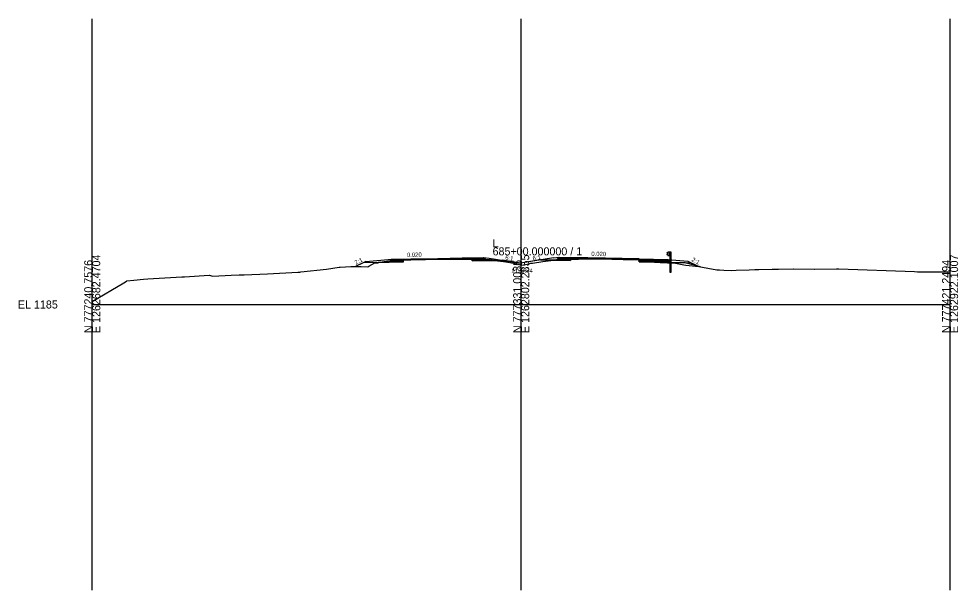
# Model space of a CAD drawing. Extents: x -41 to 1262860, y -100 to 777489.
# Drawn here: x 974.3 to 1302.8, y 970 to 1170 of the extents above; entities that cross this region are included whole.
import ezdxf

# ---------------------------------------------------------------- set-up
doc = ezdxf.new("R2010")
doc.units = 0
for name, color, linetype in [('Exist Cross Section Cell', 7, 'Continuous'), ('Exist XS Center Line Elevation Label', 7, 'Continuous'), ('Exist XS Ground Line', 7, 'Continuous'), ('Prop CMT Guardrail Graphics', 7, 'Continuous'), ('Prop CMT Pvmt Course 1', 7, 'Continuous'), ('Prop CMT Pvmt Milling', 7, 'Continuous'), ('Prop CMT Pvmt Surface', 7, 'Continuous'), ('Prop CMT Shld Paved Course 1', 7, 'Continuous'), ('Prop CMT Shld Paved Course 2', 7, 'Continuous'), ('Prop CMT Shld Paved Course 4', 7, 'Continuous'), ('Prop CMT Subgrade Earthwork', 7, 'Continuous'), ('Prop XS Earthwork Shape', 7, 'Continuous'), ('Prop XS Exc Vertical Line 1', 7, 'Continuous'), ('Prop XS Exc Vertical Line 2', 7, 'Continuous'), ('Prop XS Exc Vertical Line 3', 7, 'Continuous'), ('Prop XS Finish Grade', 7, 'Continuous'), ('Prop XS SE Text', 7, 'Continuous'), ('Prop XS Side Slope Text', 7, 'Continuous'), ('Scratch_Level_4', 7, 'Continuous'), ('Scratch_Level_5', 7, 'Continuous'), ('Scratch_Level_6', 7, 'Continuous')]:
    doc.layers.add(name, color=color, linetype=linetype)

msp = doc.modelspace()

# ---------------------------------------------------------------- linework, layer by layer
at = {"layer": 'Exist Cross Section Cell'}
for p, q in [((1150, 1070), (1150, 1090)), ((1000, 1070), (1150, 1070)), ((1150, 1070), (1300, 1070))]:
    msp.add_line(p, q, dxfattribs=at)
at = {"layer": 'Exist XS Ground Line'}
msp.add_lwpolyline([(1000, 1071.04), (1011.02, 1077.64), (1011.94, 1078.22), (1012.15, 1078.32), (1014.55, 1078.54), (1017.9, 1078.89), (1019.43, 1079), (1031.37, 1079.69), (1031.89, 1079.72), (1031.96, 1079.73), (1032.25, 1079.74), (1040.88, 1080.23), (1042.13, 1079.91), (1048.61, 1080.32), (1051.36, 1080.37), (1051.83, 1080.36), (1053.08, 1080.38), (1061.28, 1080.74), (1071.9, 1081.3), (1072.37, 1081.34), (1072.55, 1081.36), (1072.98, 1081.4), (1081.91, 1082.42), (1086.38, 1083.02), (1086.71, 1083.06), (1090.47, 1083.25), (1094.06, 1083.29), (1096.32, 1083.19), (1096.76, 1083.36), (1098.77, 1084.53), (1099.99, 1084.64), (1100.13, 1084.75), (1102.08, 1085.09), (1103.58, 1085.34), (1104.75, 1085.4), (1107.13, 1085.56), (1108.62, 1085.64), (1110.37, 1085.75), (1116.54, 1085.82), (1123.17, 1085.91), (1129.84, 1085.83), (1134.78, 1085.78), (1136.61, 1085.7), (1139.32, 1085.59), (1143.82, 1085.06), (1145.39, 1084.87), (1147.87, 1084.32), (1150.1, 1083.82), (1152.74, 1084.29), (1153.42, 1084.41), (1153.99, 1084.49), (1157.55, 1085.02), (1158.45, 1085.16), (1161.32, 1085.52), (1162.92, 1085.6), (1165.71, 1085.76), (1170.07, 1085.85), (1177.62, 1086.02), (1185.66, 1085.8), (1189.68, 1085.7), (1192.04, 1085.55), (1193.06, 1085.48), (1196.36, 1084.97), (1196.59, 1084.94), (1196.87, 1084.91), (1198.61, 1084.72), (1201.22, 1084.64), (1203.44, 1084.55), (1206.84, 1083.88), (1207.57, 1083.78), (1212.17, 1083.34), (1218.39, 1082.14), (1218.59, 1082.11), (1219.41, 1082.16), (1220.92, 1082.02), (1223.47, 1081.9), (1225.16, 1082.02), (1229.77, 1082.13), (1231.76, 1082.23), (1233.14, 1082.26), (1237.77, 1082.38), (1240, 1082.36), (1245.28, 1082.46), (1245.3, 1082.46), (1252.46, 1082.42), (1252.61, 1082.41), (1260.29, 1082.43), (1261.1, 1082.43), (1287.6, 1081.54), (1288.57, 1081.49), (1291.16, 1081.38), (1292.66, 1081.45), (1300, 1081.42)], dxfattribs=at)
at = {"layer": 'Prop CMT Guardrail Graphics'}
for p, q in [((1201.1, 1088.15), (1201.25, 1088.25)), ((1201.1, 1088.01), (1201.1, 1088.15)), ((1201.33, 1087.81), (1201.1, 1088.01)), ((1201.1, 1087.52), (1201.33, 1087.72)), ((1201.1, 1087.37), (1201.1, 1087.52)), ((1201.25, 1088.25), (1201.34, 1088.28)), ((1201.33, 1087.72), (1201.33, 1087.81)), ((1201.34, 1088.35), (1201.34, 1087.17)), ((1202.01, 1088.35), (1201.34, 1088.35)), ((1201.34, 1088.28), (1201.34, 1087.25)), ((1202.5, 1088.35), (1202.01, 1088.35)), ((1202.01, 1087.17), (1202.01, 1088.35)), ((1202.01, 1088.35), (1202.01, 1085.84)), ((1202.5, 1085.85), (1202.5, 1088.35)), ((1201.25, 1087.27), (1201.1, 1087.37)), ((1201.34, 1087.25), (1201.25, 1087.27)), ((1201.34, 1087.17), (1202.01, 1087.17)), ((1202.01, 1085.84), (1202.01, 1081.34)), ((1202.5, 1081.34), (1202.5, 1085.85)), ((1202.01, 1081.34), (1202.5, 1081.34))]:
    msp.add_line(p, q, dxfattribs=at)
at = {"layer": 'Prop CMT Pvmt Course 1'}
msp.add_line((1132.87, 1086.09), (1137.11, 1086.16), dxfattribs=at)
for points in [[(1108.73, 1085.89), (1108.73, 1085.89), (1109.11, 1085.9), (1109.72, 1085.91), (1109.72, 1085.91), (1110.51, 1085.92), (1110.51, 1085.92), (1111.39, 1085.94), (1111.39, 1085.94), (1111.39, 1085.94), (1112.25, 1085.96), (1112.25, 1085.96), (1112.99, 1085.97), (1112.99, 1085.97), (1113.51, 1085.98), (1113.51, 1085.98), (1120.81, 1086.13), (1120.81, 1086.13), (1129.33, 1086.28), (1129.33, 1086.28), (1132.87, 1086.34), (1132.87, 1086.34), (1132.87, 1086.09), (1129.33, 1086.03), (1129.33, 1086.03), (1120.81, 1085.88), (1120.81, 1085.88), (1113.51, 1085.73), (1113.51, 1085.73), (1112.99, 1085.72), (1112.99, 1085.72), (1112.25, 1085.71), (1112.25, 1085.71), (1111.39, 1085.69), (1111.39, 1085.69), (1111.39, 1085.69), (1110.51, 1085.67), (1110.51, 1085.67), (1109.72, 1085.66), (1109.72, 1085.66), (1109.11, 1085.65), (1108.73, 1085.64), (1108.73, 1085.89)], [(1191.29, 1085.95), (1191.29, 1085.95), (1179.5, 1086.19), (1179.5, 1086.19), (1167.27, 1086.43), (1167.27, 1086.43), (1167.27, 1086.43), (1167.27, 1086.18), (1167.27, 1086.18), (1179.5, 1085.94), (1179.5, 1085.94), (1191.29, 1085.7), (1191.29, 1085.95)]]:
    msp.add_lwpolyline(points, dxfattribs=at)
at = {"layer": 'Prop CMT Pvmt Milling'}
for points in [[(1132.81, 1085.8), (1129.84, 1085.83), (1129.84, 1085.83), (1129.33, 1085.84), (1123.17, 1085.91), (1123.17, 1085.91), (1123.17, 1085.91), (1120.81, 1085.88), (1116.54, 1085.82), (1116.54, 1085.82), (1113.51, 1085.79), (1112.99, 1085.78), (1112.99, 1085.78), (1112.99, 1085.78), (1112.25, 1085.77), (1112.25, 1085.77), (1111.39, 1085.76), (1111.39, 1085.76), (1110.51, 1085.75), (1110.37, 1085.75), (1110.37, 1085.75), (1110.37, 1085.75), (1109.72, 1085.71), (1109.72, 1085.71), (1109.72, 1085.71), (1109.11, 1085.67), (1108.73, 1085.65), (1108.73, 1085.65), (1108.73, 1085.64), (1109.11, 1085.65), (1109.72, 1085.66), (1109.72, 1085.66), (1109.72, 1085.66), (1110.37, 1085.67), (1110.37, 1085.67), (1110.37, 1085.67), (1110.51, 1085.67), (1111.39, 1085.69), (1111.39, 1085.69), (1112.25, 1085.71), (1112.25, 1085.71), (1112.99, 1085.72), (1112.99, 1085.72), (1112.99, 1085.72), (1113.51, 1085.73), (1116.54, 1085.79), (1116.54, 1085.79), (1120.67, 1085.88), (1120.81, 1085.88), (1123.17, 1085.91), (1123.17, 1085.91), (1123.17, 1085.91), (1123.17, 1085.91), (1129.33, 1085.84), (1129.84, 1085.83), (1129.84, 1085.83), (1132.81, 1085.8)], [(1167.5, 1085.79), (1170.07, 1085.85), (1170.07, 1085.85), (1177.62, 1086.02), (1177.62, 1086.02), (1179.5, 1085.97), (1185.66, 1085.8), (1185.66, 1085.8), (1189.68, 1085.7), (1189.68, 1085.7), (1189.68, 1085.7), (1191.5, 1085.58), (1191.5, 1085.58)], [(1167.5, 1085.79), (1170.07, 1085.85), (1170.07, 1085.85), (1176.64, 1085.99), (1177.62, 1085.97), (1177.62, 1085.97), (1177.62, 1085.97), (1179.5, 1085.94), (1179.5, 1085.94), (1184.03, 1085.85), (1184.03, 1085.85), (1185.66, 1085.8), (1189.68, 1085.7), (1189.68, 1085.7), (1189.68, 1085.7), (1191.5, 1085.58), (1191.5, 1085.58)]]:
    msp.add_lwpolyline(points, dxfattribs=at)
at = {"layer": 'Prop CMT Pvmt Surface'}
for p, q in [((1104.82, 1085.81), (1108.73, 1085.89)), ((1108.73, 1085.89), (1120.81, 1086.13)), ((1120.81, 1086.13), (1132.87, 1086.34)), ((1132.87, 1086.34), (1136.84, 1086.41)), ((1163.28, 1086.51), (1179.5, 1086.19)), ((1179.5, 1086.19), (1191.29, 1085.95)), ((1191.29, 1085.95), (1201.29, 1085.75))]:
    msp.add_line(p, q, dxfattribs=at)
at = {"layer": 'Prop CMT Shld Paved Course 1'}
for p, q in [((1132.87, 1086.34), (1132.87, 1086.34)), ((1132.87, 1086.34), (1132.87, 1086.34)), ((1132.87, 1086.34), (1132.87, 1086.09)), ((1137.11, 1086.16), (1136.84, 1086.41)), ((1163.28, 1086.51), (1163.03, 1086.27)), ((1163.03, 1086.27), (1167.27, 1086.18)), ((1167.27, 1086.43), (1167.27, 1086.43)), ((1167.27, 1086.43), (1167.27, 1086.43)), ((1167.27, 1086.43), (1167.27, 1086.18)), ((1167.27, 1086.43), (1167.27, 1086.43)), ((1167.27, 1086.18), (1167.27, 1086.18)), ((1191.29, 1085.95), (1191.29, 1085.95)), ((1191.29, 1085.95), (1191.29, 1085.95)), ((1191.29, 1085.95), (1191.29, 1085.7)), ((1191.29, 1085.7), (1191.29, 1085.7)), ((1191.29, 1085.7), (1201.55, 1085.5)), ((1195.29, 1085.87), (1195.29, 1085.87)), ((1201.55, 1085.5), (1201.29, 1085.75))]:
    msp.add_line(p, q, dxfattribs=at)
msp.add_lwpolyline([(1104.82, 1085.81), (1108.73, 1085.89), (1108.73, 1085.89), (1108.73, 1085.64), (1104.57, 1085.56), (1104.57, 1085.56), (1104.57, 1085.56), (1104.82, 1085.81), (1104.82, 1085.81)], dxfattribs=at)
at = {"layer": 'Prop CMT Shld Paved Course 2'}
for p, q in [((1132.87, 1086.09), (1132.87, 1085.76)), ((1132.87, 1085.76), (1137.46, 1085.83)), ((1137.46, 1085.84), (1137.11, 1086.16)), ((1162.71, 1085.94), (1163.03, 1086.27)), ((1162.71, 1085.94), (1167.27, 1085.85)), ((1167.27, 1086.18), (1167.27, 1086.18)), ((1167.27, 1086.18), (1167.27, 1086.18)), ((1167.27, 1086.18), (1167.27, 1085.85)), ((1167.27, 1085.85), (1167.27, 1085.85)), ((1191.29, 1085.7), (1191.29, 1085.7)), ((1191.29, 1085.7), (1191.29, 1085.7)), ((1191.29, 1085.7), (1191.29, 1085.37)), ((1191.29, 1085.37), (1191.29, 1085.37)), ((1191.29, 1085.37), (1201.89, 1085.16)), ((1201.89, 1085.16), (1201.55, 1085.5))]:
    msp.add_line(p, q, dxfattribs=at)
for points in [[(1104.57, 1085.56), (1108.73, 1085.64), (1108.73, 1085.64), (1108.73, 1085.31), (1104.23, 1085.22), (1104.23, 1085.22), (1104.23, 1085.22), (1104.57, 1085.56), (1104.57, 1085.56)], [(1108.73, 1085.64), (1109.11, 1085.65), (1109.72, 1085.66), (1109.72, 1085.66), (1109.72, 1085.66), (1110.37, 1085.67), (1110.37, 1085.67), (1110.37, 1085.67), (1110.51, 1085.67), (1111.39, 1085.69), (1111.39, 1085.69), (1112.25, 1085.71), (1112.25, 1085.71), (1112.99, 1085.72), (1112.99, 1085.72), (1112.99, 1085.72), (1113.51, 1085.73), (1116.54, 1085.79), (1116.54, 1085.79), (1120.67, 1085.88), (1120.81, 1085.88), (1123.17, 1085.91), (1123.17, 1085.91), (1123.17, 1085.91), (1123.17, 1085.91), (1129.33, 1085.84), (1129.84, 1085.83), (1129.84, 1085.83), (1132.87, 1085.8), (1132.87, 1086.09), (1132.87, 1086.09), (1129.84, 1086.04), (1129.84, 1086.04), (1129.33, 1086.03), (1123.17, 1085.92), (1123.17, 1085.92), (1123.17, 1085.92), (1120.81, 1085.88), (1116.54, 1085.79), (1116.54, 1085.79), (1113.51, 1085.73), (1112.99, 1085.72), (1112.99, 1085.72), (1112.99, 1085.72), (1112.25, 1085.71), (1112.25, 1085.71), (1111.39, 1085.69), (1111.39, 1085.69), (1110.51, 1085.67), (1110.37, 1085.67), (1110.37, 1085.67), (1110.37, 1085.67), (1109.72, 1085.66), (1109.72, 1085.66), (1109.72, 1085.66), (1109.11, 1085.65), (1108.73, 1085.64)], [(1191.29, 1085.7), (1191.29, 1085.7), (1191.29, 1085.7), (1191.29, 1085.6), (1191.29, 1085.6), (1189.68, 1085.7), (1189.68, 1085.7), (1189.68, 1085.7), (1185.66, 1085.8), (1184.03, 1085.85), (1184.03, 1085.85), (1179.5, 1085.94), (1179.5, 1085.94), (1177.62, 1085.97), (1177.62, 1085.97), (1177.62, 1085.97), (1176.64, 1085.99), (1170.07, 1085.85), (1170.07, 1085.85), (1168.66, 1085.82), (1168.66, 1085.82), (1167.27, 1085.85), (1167.27, 1086.18), (1167.27, 1086.18), (1170.07, 1086.13), (1170.07, 1086.13), (1177.62, 1085.97), (1177.62, 1085.97), (1179.5, 1085.94), (1185.66, 1085.81), (1185.66, 1085.81), (1189.68, 1085.73), (1189.68, 1085.73), (1189.68, 1085.73), (1191.29, 1085.7)]]:
    msp.add_lwpolyline(points, dxfattribs=at)
at = {"layer": 'Prop CMT Shld Paved Course 4'}
for p, q in [((1132.87, 1085.76), (1132.87, 1085.3)), ((1132.87, 1085.3), (1137.95, 1085.38)), ((1137.95, 1085.38), (1137.46, 1085.84)), ((1162.26, 1085.49), (1162.71, 1085.94)), ((1162.26, 1085.49), (1167.27, 1085.39)), ((1167.27, 1085.85), (1167.27, 1085.85)), ((1167.27, 1085.85), (1167.27, 1085.85)), ((1167.27, 1085.85), (1167.27, 1085.39)), ((1168.66, 1085.82), (1167.27, 1085.79)), ((1191.29, 1085.37), (1191.29, 1085.37)), ((1191.29, 1085.37), (1191.29, 1085.37)), ((1191.29, 1085.37), (1191.29, 1084.91)), ((1191.29, 1084.91), (1207.3, 1084.59)), ((1202.36, 1084.69), (1201.89, 1085.16))]:
    msp.add_line(p, q, dxfattribs=at)
msp.add_lwpolyline([(1104.23, 1085.22), (1108.73, 1085.31), (1108.73, 1085.31), (1108.73, 1084.85), (1103.76, 1084.75), (1103.76, 1084.75), (1103.76, 1084.75), (1104.23, 1085.22), (1104.23, 1085.22), (1104.23, 1085.22), (1104.23, 1085.22)], dxfattribs=at)
at = {"layer": 'Prop CMT Subgrade Earthwork'}
for p, q in [((1108.73, 1084.85), (1094.7, 1084.57)), ((1108.73, 1085.65), (1108.73, 1084.85)), ((1132.87, 1085.8), (1132.87, 1085.3)), ((1132.87, 1085.3), (1143.45, 1085.48)), ((1156.76, 1085.6), (1167.27, 1085.39)), ((1167.27, 1085.39), (1167.27, 1085.79)), ((1191.29, 1085.6), (1191.29, 1084.91)), ((1191.29, 1084.91), (1209.57, 1084.54))]:
    msp.add_line(p, q, dxfattribs=at)
at = {"layer": 'Prop XS Earthwork Shape'}
for points in [[(1098.77, 1084.53), (1099.99, 1084.64), (1100.04, 1084.67), (1094.7, 1084.57), (1092.11, 1083.27), (1094.06, 1083.29), (1096.32, 1083.19), (1096.76, 1083.36)], [(1103.77, 1084.75), (1100.04, 1084.67), (1100.13, 1084.75), (1102.08, 1085.09), (1103.58, 1085.34), (1104.4, 1085.38)], [(1108.73, 1085.65), (1108.73, 1084.85), (1103.77, 1084.75), (1104.4, 1085.38), (1104.75, 1085.4), (1107.13, 1085.56), (1108.62, 1085.64)], [(1134.78, 1085.78), (1136.61, 1085.7), (1137.65, 1085.66), (1137.95, 1085.38), (1132.87, 1085.3), (1132.87, 1085.8)], [(1137.95, 1085.38), (1140.68, 1085.43), (1139.32, 1085.59), (1137.65, 1085.66)], [(1156.76, 1085.6), (1149.75, 1084.43), (1143.45, 1085.48), (1140.68, 1085.43), (1143.82, 1085.06), (1145.39, 1084.87), (1147.87, 1084.32), (1150.1, 1083.82), (1152.74, 1084.29), (1153.42, 1084.41), (1153.99, 1084.49), (1157.55, 1085.02), (1158.45, 1085.16), (1161.26, 1085.51)], [(1161.32, 1085.52), (1162.34, 1085.57), (1162.26, 1085.49), (1161.26, 1085.51)], [(1167.27, 1085.39), (1167.27, 1085.79), (1165.71, 1085.76), (1162.92, 1085.6), (1162.34, 1085.57), (1162.26, 1085.49)], [(1192.04, 1085.55), (1193.06, 1085.48), (1196.36, 1084.97), (1196.59, 1084.94), (1196.87, 1084.91), (1198.16, 1084.77), (1191.29, 1084.91), (1191.29, 1085.6)], [(1201.22, 1084.64), (1203.44, 1084.55), (1206.84, 1083.88), (1207.57, 1083.78), (1212.17, 1083.34), (1212.73, 1083.23), (1207.3, 1084.59), (1202.36, 1084.69), (1198.16, 1084.77), (1198.61, 1084.72)]]:
    msp.add_lwpolyline(points, close=True, dxfattribs=at)
at = {"layer": 'Prop XS Exc Vertical Line 1'}
msp.add_line((1000, 970), (1000, 1170), dxfattribs=at)
at = {"layer": 'Prop XS Exc Vertical Line 2'}
msp.add_line((1150, 970), (1150, 1170), dxfattribs=at)
at = {"layer": 'Prop XS Exc Vertical Line 3'}
msp.add_line((1300, 970), (1300, 1170), dxfattribs=at)
at = {"layer": 'Prop XS Finish Grade'}
for p, q in [((1095.73, 1085.08), (1092.11, 1083.27)), ((1095.73, 1085.08), (1104.82, 1085.81)), ((1103.77, 1084.75), (1104.82, 1085.81)), ((1136.84, 1086.41), (1138.84, 1086.25)), ((1137.95, 1085.38), (1136.84, 1086.41)), ((1138.84, 1086.25), (1149.75, 1084.43)), ((1161.27, 1086.35), (1149.75, 1084.43)), ((1161.27, 1086.35), (1163.28, 1086.51)), ((1163.28, 1086.51), (1162.26, 1085.49)), ((1201.29, 1085.75), (1208.28, 1085.19)), ((1201.29, 1085.75), (1202.36, 1084.69)), ((1208.28, 1085.19), (1211.94, 1083.36))]:
    msp.add_line(p, q, dxfattribs=at)
at = {"layer": 'Scratch_Level_4'}
msp.add_line((1300, 970), (1300, 1170), dxfattribs=at)
at = {"layer": 'Scratch_Level_5'}
msp.add_line((1150, 1074.01), (1150, 1108.31), dxfattribs=at)
at = {"layer": 'Scratch_Level_6'}
msp.add_line((1000, 970), (1000, 1170), dxfattribs=at)

# ---------------------------------------------------------------- texts
at = {"layer": 'Exist Cross Section Cell'}
for s, p in [('L', (1140, 1090)), ('685+00.000000 / 1', (1140, 1087.2)), ('EL 1185', (974, 1068.6))]:
    msp.add_text(s, height=2.8, dxfattribs=at).set_placement(p)
for s, p in [('N 777240.7576', (1000, 1060)), ('E 1262682.4704', (1002.8, 1060)), ('N 777331.0035', (1150, 1060)), ('E 1262802.2855', (1152.8, 1060)), ('N 777421.2494', (1300, 1060)), ('E 1262922.1007', (1302.8, 1060))]:
    msp.add_text(s, height=2.8, rotation=90, dxfattribs=at).set_placement(p)
at = {"layer": 'Exist XS Center Line Elevation Label'}
msp.add_text('1198.84', height=1.5, dxfattribs=at).set_placement((1146.56, 1081.09))
at = {"layer": 'Prop XS SE Text'}
for rotation, p in [(1.1458, (1110.06, 1086.62)), (358.8542, (1174.53, 1087.01))]:
    msp.add_text('0.020', height=1.5, rotation=rotation, dxfattribs=at).set_placement(p)
at = {"layer": 'Prop XS Side Slope Text'}
for s, rotation, p in [('2:1', 26.5651, (1092.17, 1083.86)), ('6:1', 350.5377, (1144.33, 1085.75)), ('6:1', 9.4623, (1154.11, 1085.4)), ('2:1', 332.1263, (1209.42, 1085.25))]:
    msp.add_text(s, height=1.5, rotation=rotation, dxfattribs=at).set_placement(p)

doc.saveas('drawing.dxf')
